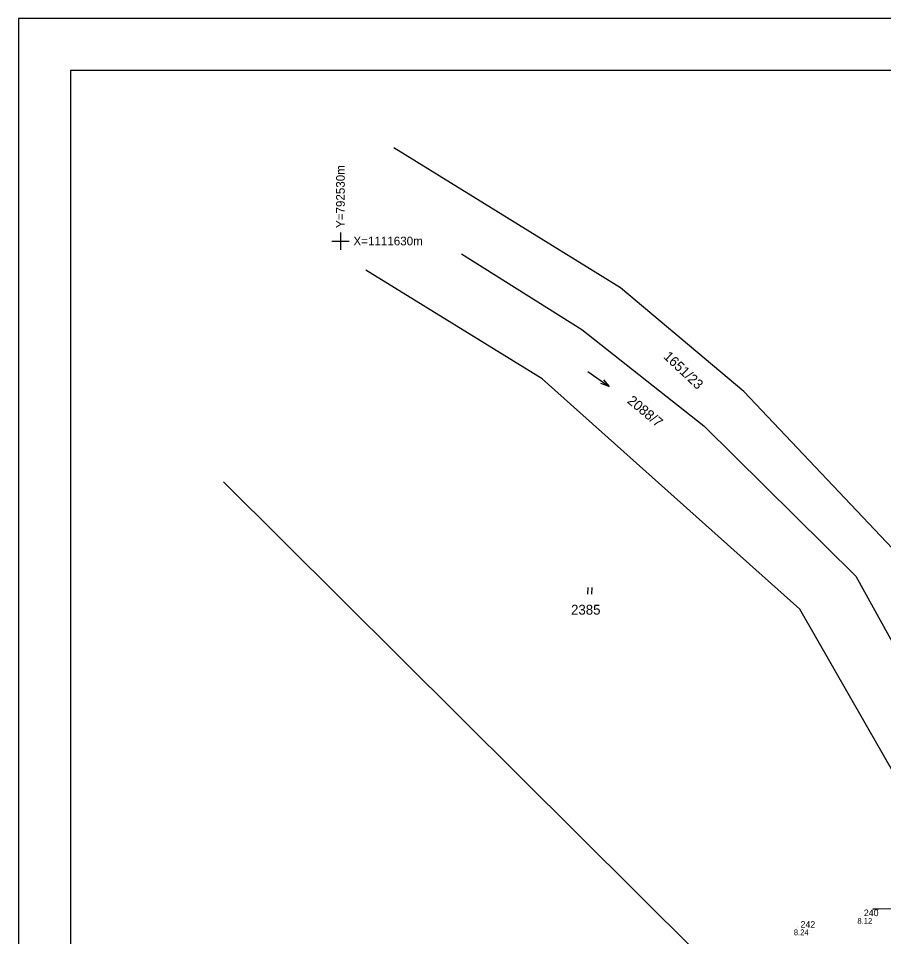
# Model space of a CAD drawing. Extents: x -792549 to -792339, y -1111914 to -1111617.
# Drawn here: x -792548.6 to -792498.7, y -1111670.1 to -1111617.2 of the extents above; entities that cross this region are included whole.
import ezdxf

# ---------------------------------------------------------------- set-up
doc = ezdxf.new("R2010")
doc.units = 0
for name, color, linetype in [('Vrstva 1', 7, 'Continuous'), ('Vrstva 24', 7, 'Continuous'), ('Vrstva 32', 7, 'Continuous'), ('Vrstva 41', 7, 'Continuous'), ('Vrstva 42', 7, 'Continuous'), ('Vrstva 45', 7, 'Continuous'), ('Vrstva 48', 7, 'Continuous'), ('Vrstva 49', 7, 'Continuous'), ('Vrstva 50', 7, 'Continuous'), ('Vrstva 60', 7, 'Continuous')]:
    doc.layers.add(name, color=color, linetype=linetype)

# ---------------------------------------------------------------- blocks, each defined once
blk = doc.blocks.new('3$0600')
at = {"layer": 'Vrstva 1'}
for p, q in [((-5, 15), (-5, 0)), ((5, 0), (5, 15))]:
    blk.add_line(p, q, dxfattribs=at)
blk = doc.blocks.new('8$0210')
at = {"layer": 'Vrstva 1'}
blk.add_line((-30, 0), (30, 0), dxfattribs=at)
blk.add_lwpolyline([(10, 5), (30, 0), (10, -5)], dxfattribs=at)
blk = doc.blocks.new('SC6231')
at = {"layer": 'Vrstva 1'}
blk.add_line((0, 0), (0, 0), dxfattribs=at)
blk = doc.blocks.new('$408')
at = {"layer": 'Vrstva 1'}
for p, q in [((-20, 0), (20, 0)), ((0, 20), (0, -20))]:
    blk.add_line(p, q, dxfattribs=at)

msp = doc.modelspace()

# ---------------------------------------------------------------- linework, layer by layer
at = {"layer": 'Vrstva 24'}
msp.add_lwpolyline([(-792545.564, -1111620.164), (-792545.564, -1111911.164), (-792341.564, -1111911.164), (-792341.564, -1111620.164)], close=True, dxfattribs=at)
at = {"layer": 'Vrstva 32'}
msp.add_lwpolyline([(-792497.046, -1111668.435), (-792498.243, -1111668.503), (-792498.992, -1111668.52), (-792499.311, -1111668.516)], dxfattribs=at)
at = {"layer": 'Vrstva 41'}
for points in [[(-792523.029, -1111630.747), (-792516.09, -1111635.11), (-792509.06, -1111640.65), (-792500.3, -1111649.32), (-792481.68, -1111682.99), (-792478.83, -1111682.26), (-792498.18, -1111647.73), (-792506.75, -1111638.68), (-792513.86, -1111632.7), (-792526.925, -1111624.621)], [(-792475.81, -1111712.09), (-792476.33, -1111699.64), (-792484.69, -1111684.09), (-792503.52, -1111651.22), (-792518.38, -1111637.95), (-792528.528, -1111631.688)], [(-792536.737, -1111643.89), (-792506.06, -1111674.4), (-792485.77, -1111711.57), (-792480.39, -1111721.44), (-792475.74, -1111713.71), (-792475.81, -1111712.09), (-792485.77, -1111711.57)]]:
    msp.add_lwpolyline(points, dxfattribs=at)
at = {"layer": 'Vrstva 60'}
msp.add_lwpolyline([(-792548.564, -1111617.164), (-792548.564, -1111914.164), (-792338.564, -1111914.164), (-792338.564, -1111617.164), (-792548.564, -1111617.164)], dxfattribs=at)

# ---------------------------------------------------------------- block references
at = {"layer": 'Vrstva 42', "yscale": 0.025000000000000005}
for name, p, xscale, rotation in [('8$0210', (-792515.12, -1111637.96), 0.025, -35.01591200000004), ('3$0600', (-792515.625, -1111650.354), 0.025000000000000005, -1.1963577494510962)]:
    msp.add_blockref(name, p, dxfattribs=dict(at, xscale=xscale, rotation=rotation))
at = {"layer": 'Vrstva 45', "xscale": 0.025, "yscale": 0.025000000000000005}
msp.add_blockref('$408', (-792530, -1111630), dxfattribs=at)
at = {"layer": 'Vrstva 48', "xscale": 0.1, "yscale": 0.10000000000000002}
for p in [(-792500.03, -1111668.92), (-792503.68, -1111669.58)]:
    msp.add_blockref('SC6231', p, dxfattribs=at)

# ---------------------------------------------------------------- texts
at = {"layer": 'Vrstva 42'}
for s, rotation, p in [('1651/23', 316.742, (-792511.423, -1111636.711)), ('2088/7', 320.294, (-792513.508, -1111639.291))]:
    msp.add_text(s, height=0.57, rotation=rotation, dxfattribs=at).set_placement(p)
msp.add_text('2385', height=0.57, dxfattribs=at).set_placement((-792516.706, -1111651.54))
at = {"layer": 'Vrstva 45'}
msp.add_text('Y=792530m', height=0.5, rotation=90.012, dxfattribs=at).set_placement((-792529.75, -1111629.25))
msp.add_text('X=1111630m', height=0.5, dxfattribs=at).set_placement((-792529.25, -1111630.25))
at = {"layer": 'Vrstva 49'}
for s, p in [('240', (-792499.831, -1111668.92)), ('242', (-792503.481, -1111669.59))]:
    msp.add_text(s, height=0.38, dxfattribs=at).set_placement(p)
at = {"layer": 'Vrstva 50'}
for s, p in [('8.12', (-792500.203, -1111669.36)), ('8.24', (-792503.869, -1111670.02))]:
    msp.add_text(s, height=0.33, dxfattribs=at).set_placement(p)

doc.saveas('drawing.dxf')
